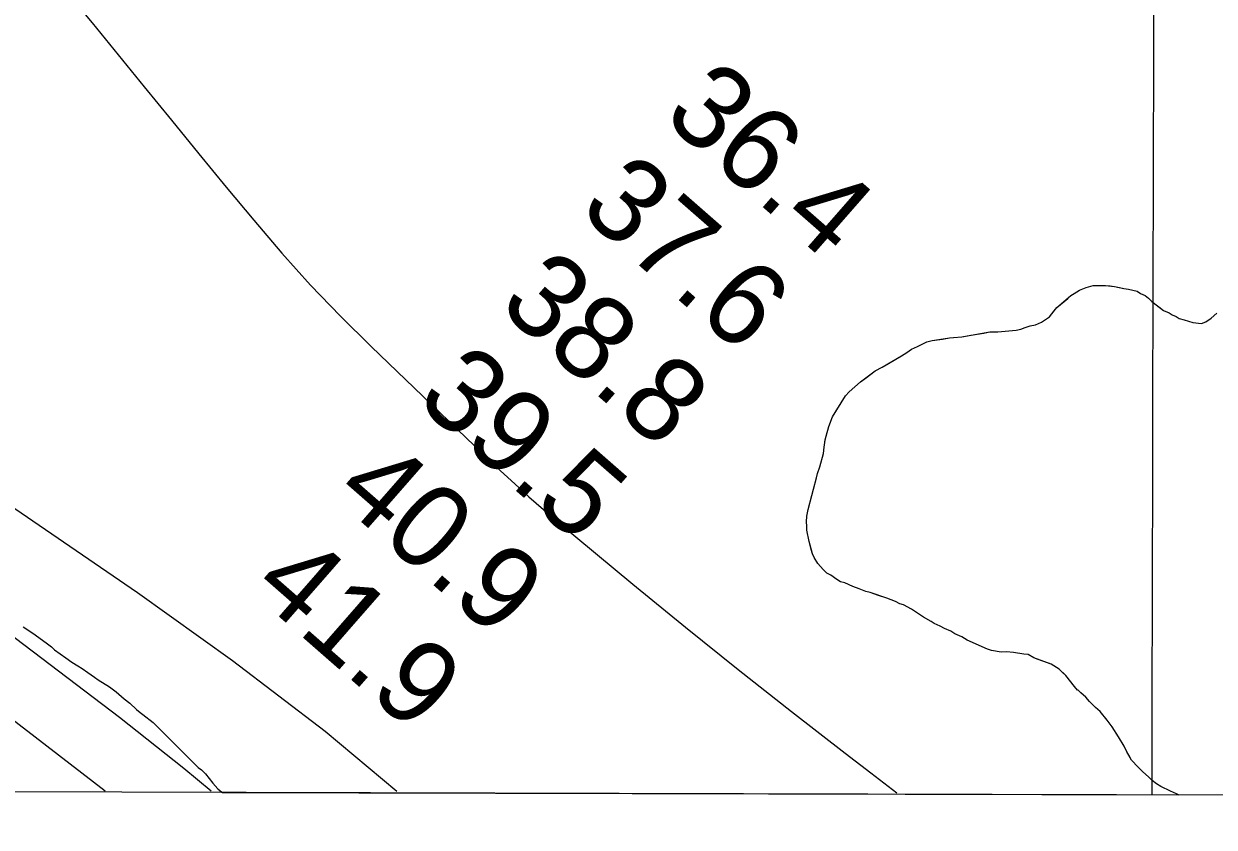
# Model space of a CAD drawing. Extents: x 3172231 to 3210228, y 940198 to 965780.
# Drawn here: x 3196456 to 3197406, y 945652 to 946293 of the extents above; entities that cross this region are included whole.
import ezdxf

# ---------------------------------------------------------------- set-up
doc = ezdxf.new("R2010")
doc.units = 0
for name, color, linetype in [('V-GRID-FRAM', 7, 'Continuous'), ('V-GRID-MAJR', 7, 'Continuous'), ('V-RIVR-RANG', 7, 'Continuous'), ('V-SITE-VEGE', 7, 'Continuous'), ('V-TOPO-MAJR', 7, 'Continuous'), ('V-TOPO-MINR', 7, 'Continuous'), ('V-TOPO-SHOR', 7, 'Continuous')]:
    doc.layers.add(name, color=color, linetype=linetype)

msp = doc.modelspace()

# ---------------------------------------------------------------- linework, layer by layer
at = {"layer": 'V-GRID-FRAM'}
msp.add_lwpolyline([(3176539.592, 963919.479), (3207827.662, 963842.116), (3207790.623, 945652.442), (3176486.679, 945729.845), (3176539.592, 963919.479)], dxfattribs=at)
at = {"layer": 'V-GRID-MAJR'}
msp.add_spline([(3197355.974, 945678.243), (3197370.077, 951738.379), (3197384.187, 957801.599), (3197398.298, 963864.87), (3197398.305, 963867.904)], degree=3, dxfattribs=at)
at = {"layer": 'V-SITE-VEGE'}
for p, q in [((3197293.878, 946078.066), (3197298.171, 946080.651)), ((3197298.171, 946080.651), (3197303.324, 946082.805)), ((3197303.324, 946082.805), (3197308.909, 946084.538)), ((3197308.909, 946084.538), (3197318.794, 946084.556)), ((3197318.794, 946084.556), (3197326.101, 946083.708)), ((3197326.101, 946083.708), (3197333.409, 946082.004)), ((3197333.409, 946082.004), (3197337.279, 946081.58)), ((3197337.279, 946081.58), (3197344.159, 946079.874)), ((3197344.159, 946079.874), (3197346.741, 946078.16)), ((3197280.144, 946066.863), (3197291.302, 946076.34)), ((3197291.302, 946076.34), (3197293.878, 946078.066)), ((3197346.741, 946078.16), (3197350.612, 946076.448)), ((3197350.612, 946076.448), (3197353.194, 946074.304)), ((3197353.194, 946074.304), (3197355.779, 946071.73)), ((3197355.779, 946071.73), (3197365.247, 946064.441)), ((3197274.142, 946059.548), (3197280.144, 946066.863)), ((3197365.247, 946064.441), (3197369.548, 946062.731)), ((3197369.548, 946062.731), (3197372.13, 946061.014)), ((3197372.13, 946061.014), (3197375.141, 946059.732)), ((3197375.141, 946059.732), (3197377.725, 946058.016)), ((3197403.08, 946058.493), (3197407.8, 946062.37)), ((3197251.382, 946049.619), (3197254.817, 946050.916)), ((3197254.817, 946050.916), (3197258.683, 946052.212)), ((3197258.683, 946052.212), (3197262.978, 946053.078)), ((3197262.978, 946053.078), (3197267.703, 946055.237)), ((3197267.703, 946055.237), (3197274.142, 946059.548)), ((3197377.725, 946058.016), (3197381.592, 946057.164)), ((3197381.592, 946057.164), (3197388.473, 946055.028)), ((3197388.473, 946055.028), (3197395.35, 946054.18)), ((3197395.35, 946054.18), (3197398.787, 946055.477)), ((3197398.787, 946055.477), (3197403.08, 946058.493)), ((3197180.485, 946040.465), (3197194.233, 946042.64)), ((3197194.233, 946042.64), (3197197.671, 946043.074)), ((3197197.671, 946043.074), (3197204.116, 946043.514)), ((3197204.116, 946043.514), (3197226.458, 946047.426)), ((3197226.458, 946047.426), (3197232.905, 946047.436)), ((3197232.905, 946047.436), (3197247.516, 946048.753)), ((3197247.516, 946048.753), (3197251.382, 946049.619)), ((3197160.304, 946030.97), (3197164.164, 946033.557)), ((3197164.164, 946033.557), (3197168.889, 946035.715)), ((3197168.889, 946035.715), (3197173.181, 946037.872)), ((3197173.181, 946037.872), (3197176.188, 946039.594)), ((3197176.188, 946039.594), (3197180.485, 946040.465)), ((3197140.553, 946019.331), (3197156.009, 946028.386)), ((3197156.009, 946028.386), (3197160.304, 946030.97)), ((3197123.382, 946007.695), (3197134.972, 946016.313)), ((3197134.972, 946016.313), (3197140.553, 946019.331)), ((3197114.371, 945999.513), (3197123.382, 946007.695)), ((3197101.086, 945979.719), (3197111.369, 945996.498)), ((3197111.369, 945996.498), (3197114.371, 945999.513)), ((3197098.091, 945971.978), (3197101.086, 945979.719)), ((3197095.101, 945961.23), (3197098.091, 945971.978)), ((3197093.834, 945950.48), (3197094.254, 945955.639)), ((3197094.254, 945955.639), (3197095.101, 945961.23)), ((3197090.844, 945939.73), (3197093.834, 945950.48)), ((3197089.134, 945934.567), (3197090.844, 945939.73)), ((3197085.722, 945922.099), (3197088.282, 945931.128)), ((3197088.282, 945931.128), (3197089.134, 945934.567)), ((3197084.44, 945916.94), (3197085.722, 945922.099)), ((3197081.451, 945905.76), (3197084.44, 945916.94)), ((3197080.18, 945895.872), (3197080.602, 945900.601)), ((3197080.602, 945900.601), (3197081.451, 945905.76)), ((3197080.616, 945892.433), (3197080.18, 945895.872)), ((3197080.62, 945889.427), (3197080.616, 945892.433)), ((3197082.357, 945880.403), (3197080.62, 945889.427)), ((3197084.954, 945870.524), (3197082.357, 945880.403)), ((3197086.25, 945867.517), (3197084.954, 945870.524)), ((3197089.267, 945862.795), (3197086.25, 945867.517)), ((3197093.574, 945858.076), (3197089.267, 945862.795)), ((3197096.586, 945855.074), (3197093.574, 945858.076)), ((3197099.599, 945853.359), (3197096.586, 945855.074)), ((3197104.332, 945849.929), (3197099.599, 945853.359)), ((3197107.344, 945848.217), (3197104.332, 945849.929)), ((3197110.785, 945847.363), (3197107.344, 945848.217)), ((3197117.236, 945844.367), (3197110.785, 945847.363)), ((3197122.397, 945842.657), (3197117.236, 945844.367)), ((3197127.56, 945840.516), (3197122.397, 945842.657)), ((3197130.999, 945839.664), (3197127.56, 945840.516)), ((3197144.329, 945834.96), (3197130.999, 945839.664)), ((3197151.21, 945832.394), (3197144.329, 945834.96)), ((3197154.651, 945830.682), (3197151.21, 945832.394)), ((3197157.662, 945829.828), (3197154.651, 945830.682)), ((3197164.115, 945826.402), (3197157.662, 945829.828)), ((3197173.583, 945819.973), (3197164.115, 945826.402)), ((3197179.606, 945816.545), (3197173.583, 945819.973)), ((3197182.189, 945814.83), (3197179.606, 945816.545)), ((3197186.919, 945812.69), (3197182.189, 945814.83)), ((3197190.362, 945810.976), (3197186.919, 945812.69)), ((3196454.987, 945812.193), (3196462.781, 945807.097)), ((3196462.781, 945807.097), (3196470.578, 945801.514)), ((3197195.521, 945808.838), (3197190.362, 945810.976)), ((3197198.534, 945806.694), (3197195.521, 945808.838)), ((3197204.127, 945804.126), (3197198.534, 945806.694)), ((3197208.43, 945801.555), (3197204.127, 945804.126)), ((3196470.578, 945801.514), (3196474.478, 945798.6)), ((3196474.478, 945798.6), (3196477.646, 945796.173)), ((3196477.646, 945796.173), (3196480.083, 945793.988)), ((3196480.083, 945793.988), (3196489.098, 945787.432)), ((3197224.773, 945794.279), (3197208.43, 945801.555)), ((3197227.783, 945793.425), (3197224.773, 945794.279)), ((3196489.098, 945787.432), (3196493.972, 945784.037)), ((3197235.523, 945792.149), (3197227.783, 945793.425)), ((3197239.819, 945792.157), (3197235.523, 945792.149)), ((3197245.408, 945791.737), (3197239.819, 945792.157)), ((3197253.578, 945790.463), (3197245.408, 945791.737)), ((3197257.016, 945790.039), (3197253.578, 945790.463)), ((3197261.747, 945787.469), (3197257.016, 945790.039)), ((3197275.51, 945782.339), (3197261.747, 945787.469)), ((3196493.972, 945784.037), (3196498.845, 945781.124)), ((3196498.845, 945781.124), (3196502.255, 945778.941)), ((3196502.255, 945778.941), (3196506.641, 945775.785)), ((3196506.641, 945775.785), (3196512.001, 945772.144)), ((3197281.965, 945778.483), (3197275.51, 945782.339)), ((3197287.13, 945773.334), (3197281.965, 945778.483)), ((3196512.001, 945772.144), (3196514.923, 945769.961)), ((3196514.923, 945769.961), (3196523.941, 945764.38)), ((3197294.024, 945764.751), (3197287.13, 945773.334)), ((3196523.941, 945764.38), (3196529.3, 945760.253)), ((3196529.3, 945760.253), (3196535.639, 945754.91)), ((3197296.608, 945761.746), (3197294.024, 945764.751)), ((3197297.036, 945761.748), (3197296.608, 945761.746)), ((3197299.191, 945759.602), (3197297.036, 945761.748)), ((3197303.066, 945756.172), (3197299.191, 945759.602)), ((3197306.078, 945752.739), (3197303.066, 945756.172)), ((3196535.639, 945754.91), (3196540.267, 945751.269)), ((3196540.267, 945751.269), (3196545.631, 945746.413)), ((3196545.631, 945746.413), (3196547.093, 945744.955)), ((3197310.815, 945748.021), (3197306.078, 945752.739)), ((3197314.69, 945744.588), (3197310.815, 945748.021)), ((3196547.093, 945744.955), (3196552.943, 945740.343)), ((3196552.943, 945740.343), (3196556.352, 945737.916)), ((3196556.352, 945737.916), (3196558.79, 945735.972)), ((3197320.287, 945737.721), (3197314.69, 945744.588)), ((3197324.164, 945732.573), (3197320.287, 945737.721)), ((3196558.79, 945735.972), (3196594.871, 945700.024)), ((3197329.339, 945724.415), (3197324.164, 945732.573)), ((3197333.65, 945717.118), (3197329.339, 945724.415)), ((3197336.239, 945711.966), (3197333.65, 945717.118)), ((3197339.69, 945705.955), (3197336.239, 945711.966)), ((3196594.871, 945700.024), (3196597.308, 945698.08)), ((3197344.855, 945700.376), (3197339.69, 945705.955)), ((3197348.732, 945696.515), (3197344.855, 945700.376)), ((3196597.308, 945698.08), (3196600.72, 945694.924)), ((3196600.72, 945694.924), (3196606.576, 945687.633)), ((3197353.037, 945692.655), (3197348.732, 945696.515)), ((3197356.049, 945689.651), (3197353.037, 945692.655)), ((3197359.492, 945687.08), (3197356.049, 945689.651)), ((3196606.576, 945687.633), (3196610.477, 945683.017)), ((3196610.477, 945683.017), (3196613.645, 945680.346)), ((3196613.645, 945680.346), (3196613.941, 945680.078)), ((3196613.941, 945680.078), (3197377.226, 945678.19)), ((3197362.935, 945684.936), (3197359.492, 945687.08)), ((3197370.678, 945681.084), (3197362.935, 945684.936)), ((3197375.409, 945678.944), (3197370.678, 945681.084)), ((3197377.226, 945678.19), (3197375.409, 945678.944))]:
    msp.add_line(p, q, dxfattribs=at)
at = {"layer": 'V-TOPO-MAJR'}
for points in [[(3196753.315, 945680.946), (3196696.221, 945728.624), (3196622.183, 945785.1), (3196546.436, 945839.435), (3195836.361, 946325.404), (3195824.472, 946333.612), (3195812.628, 946341.884), (3195800.852, 946350.252), (3195789.121, 946358.684), (3195774.474, 946369.303), (3195770.105, 946372.481), (3195765.744, 946375.669), (3195761.392, 946378.87), (3195757.048, 946382.081), (3194922.237, 946926.193), (3194913.185, 946930.845), (3194904.237, 946935.706), (3194895.462, 946940.873), (3194886.815, 946946.238), (3194878.36, 946951.901), (3194870.033, 946957.763), (3194837.981, 946981.17)], [(3196423.461, 946397.213), (3196467.073, 946345.872), (3196510.072, 946294), (3196551.685, 946242.868), (3196573.453, 946216.194), (3196595.268, 946189.56), (3196617.155, 946162.983), (3196639.089, 946136.446), (3196661.493, 946110.343), (3196684.475, 946084.777), (3196708.325, 946060.018), (3196732.752, 946035.797), (3196836.134, 945936.76), (3196847.38, 945926.216), (3196858.771, 945915.837), (3196870.383, 945905.704), (3196882.142, 945895.736), (3196941.716, 945846.32), (3196983.576, 945812.022), (3197025.706, 945778.065), (3197068.242, 945744.618), (3197111.049, 945711.512), (3197131.537, 945695.864), (3197152.393, 945679.959)]]:
    msp.add_lwpolyline(points, dxfattribs=at)
at = {"layer": 'V-TOPO-MINR'}
for points in [[(3196520.517, 945681.036), (3196395.86, 945777.173), (3196304.303, 945847.217), (3196212.387, 945916.785), (3196119.935, 945985.638), (3196027.124, 946054.013), (3195911.158, 946138.756), (3195876.017, 946164.34), (3195840.815, 946189.84), (3195805.523, 946215.214), (3195770.17, 946240.505), (3195765.826, 946243.6), (3195732.511, 946267.153), (3195699.08, 946290.537), (3195665.472, 946313.668), (3195631.747, 946336.629), (3195490.68, 946431.894), (3194735.875, 946960.727)], [(3196605.155, 945681.069), (3196583.433, 945699.208), (3196532.016, 945739.87), (3196130.161, 946044.798), (3196064.821, 946094.098), (3195999.304, 946143.159), (3195933.52, 946191.863), (3195867.559, 946240.328), (3195783.838, 946301.492), (3195759.61, 946319.204), (3195735.389, 946336.927), (3195711.18, 946354.666), (3195686.979, 946372.415), (3195550.352, 946472.687), (3195511.672, 946500.005), (3195472.37, 946526.358), (3195432.135, 946551.262), (3195391.278, 946575.201), (3194844.526, 946932.111)]]:
    msp.add_lwpolyline(points, dxfattribs=at)
at = {"layer": 'V-TOPO-SHOR'}
for points in [[(3197281.965, 945778.483), (3197275.51, 945782.339), (3197265.19, 945786.187), (3197261.747, 945787.469), (3197257.016, 945790.039), (3197253.578, 945790.463), (3197245.408, 945791.737), (3197239.819, 945792.157), (3197235.523, 945792.149), (3197227.783, 945793.425), (3197224.775, 945794.279), (3197213.16, 945799.415), (3197208.43, 945801.555), (3197204.127, 945804.126), (3197198.534, 945806.694), (3197195.521, 945808.838), (3197190.36, 945810.976), (3197186.919, 945812.69), (3197182.189, 945814.83), (3197179.606, 945816.545), (3197173.583, 945819.973), (3197164.115, 945826.402), (3197157.662, 945829.828), (3197154.651, 945830.682), (3197151.21, 945832.394), (3197144.329, 945834.96), (3197137.02, 945837.526), (3197130.999, 945839.664), (3197127.558, 945840.516), (3197122.397, 945842.657), (3197117.236, 945844.367), (3197110.785, 945847.363), (3197107.344, 945848.217), (3197104.332, 945849.929), (3197099.599, 945853.359), (3197096.586, 945855.074), (3197093.574, 945858.076), (3197089.267, 945862.795), (3197086.25, 945867.517), (3197084.954, 945870.524), (3197084.087, 945873.96), (3197082.357, 945880.403), (3197080.622, 945889.427), (3197080.616, 945892.433), (3197080.18, 945895.872), (3197080.602, 945900.601), (3197081.451, 945905.76), (3197084.44, 945916.94), (3197085.72, 945922.099), (3197088.282, 945931.128), (3197089.134, 945934.569), (3197090.844, 945939.73), (3197093.834, 945950.48), (3197094.254, 945955.639), (3197095.101, 945961.228), (3197095.955, 945964.236), (3197098.091, 945971.978), (3197101.086, 945979.719), (3197105.37, 945986.602), (3197107.94, 945990.905), (3197111.369, 945996.498), (3197114.371, 945999.513), (3197123.382, 946007.695), (3197128.105, 946011.141), (3197131.537, 946013.726), (3197134.972, 946016.313), (3197140.553, 946019.331), (3197145.705, 946022.348), (3197156.009, 946028.386), (3197160.302, 946030.97), (3197164.164, 946033.557), (3197168.889, 946035.715), (3197173.181, 946037.872), (3197176.188, 946039.596), (3197180.485, 946040.465), (3197188.648, 946041.767), (3197194.233, 946042.638), (3197197.671, 946043.074), (3197204.116, 946043.514), (3197211.42, 946044.819), (3197221.731, 946046.556), (3197226.458, 946047.426), (3197232.905, 946047.436), (3197247.516, 946048.753), (3197251.382, 946049.619), (3197254.817, 946050.916), (3197258.683, 946052.21), (3197262.978, 946053.078), (3197267.703, 946055.237), (3197274.142, 946059.546), (3197278, 946064.281), (3197280.144, 946066.863), (3197288.728, 946074.185), (3197291.302, 946076.34), (3197293.878, 946078.064), (3197298.171, 946080.651), (3197303.324, 946082.807), (3197308.909, 946084.538), (3197312.347, 946084.544), (3197315.786, 946084.55), (3197318.794, 946084.556)], [(3197318.794, 946084.556), (3197322.663, 946084.132), (3197326.101, 946083.708), (3197329.97, 946082.856), (3197333.411, 946082.004), (3197337.279, 946081.58), (3197340.72, 946080.728), (3197344.159, 946079.874), (3197346.741, 946078.16), (3197350.612, 946076.448), (3197353.194, 946074.304), (3197355.779, 946071.73), (3197361.374, 946067.441), (3197365.247, 946064.441), (3197369.548, 946062.731), (3197372.13, 946061.014), (3197375.141, 946059.732), (3197377.723, 946058.016), (3197381.592, 946057.164), (3197388.473, 946055.028), (3197395.35, 946054.18), (3197398.787, 946055.477), (3197403.08, 946058.493), (3197407.8, 946062.37)], [(3197377.226, 945678.19), (3197375.409, 945678.944), (3197370.678, 945681.084), (3197362.935, 945684.936), (3197359.492, 945687.08), (3197356.049, 945689.653), (3197353.037, 945692.655), (3197348.732, 945696.515), (3197344.855, 945700.376), (3197339.69, 945705.955), (3197337.963, 945708.959), (3197336.239, 945711.966), (3197333.65, 945717.116), (3197329.339, 945724.415), (3197324.166, 945732.573), (3197320.289, 945737.721), (3197314.69, 945744.588), (3197310.815, 945748.021), (3197306.078, 945752.739), (3197303.066, 945756.172), (3197299.191, 945759.602), (3197297.036, 945761.748), (3197296.608, 945761.746), (3197294.024, 945764.751), (3197287.13, 945773.334), (3197284.548, 945775.908), (3197281.965, 945778.483)]]:
    msp.add_lwpolyline(points, dxfattribs=at)

# ---------------------------------------------------------------- texts
at = {"layer": 'V-RIVR-RANG'}
for s, p in [('36.4', (3196964.185, 946217.916)), ('37.6', (3196897.148, 946143.698)), ('38.8', (3196832.889, 946067.047)), ('39.5', (3196767.241, 945991.613)), ('40.9', (3196701.395, 945916.352)), ('41.9', (3196635.747, 945840.918))]:
    msp.add_text(s, height=67, rotation=318.828326, dxfattribs=at).set_placement(p)

doc.saveas('drawing.dxf')
